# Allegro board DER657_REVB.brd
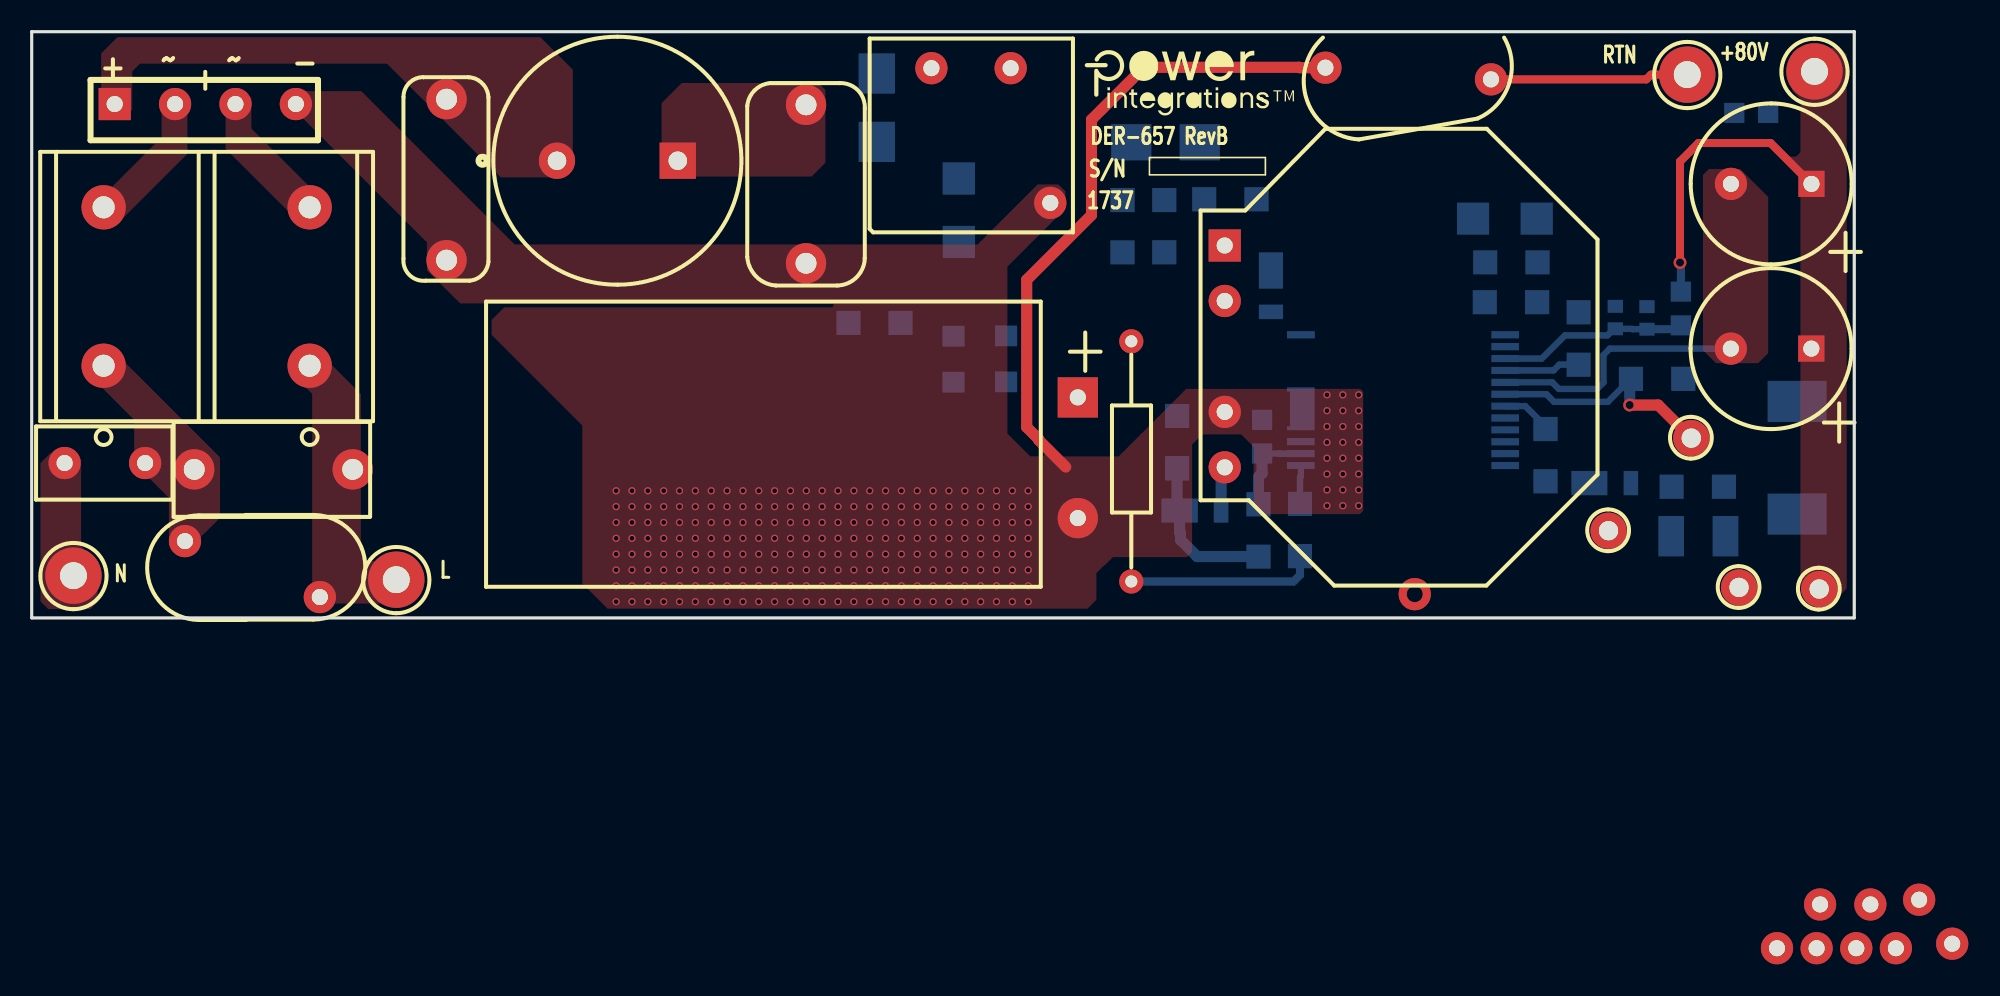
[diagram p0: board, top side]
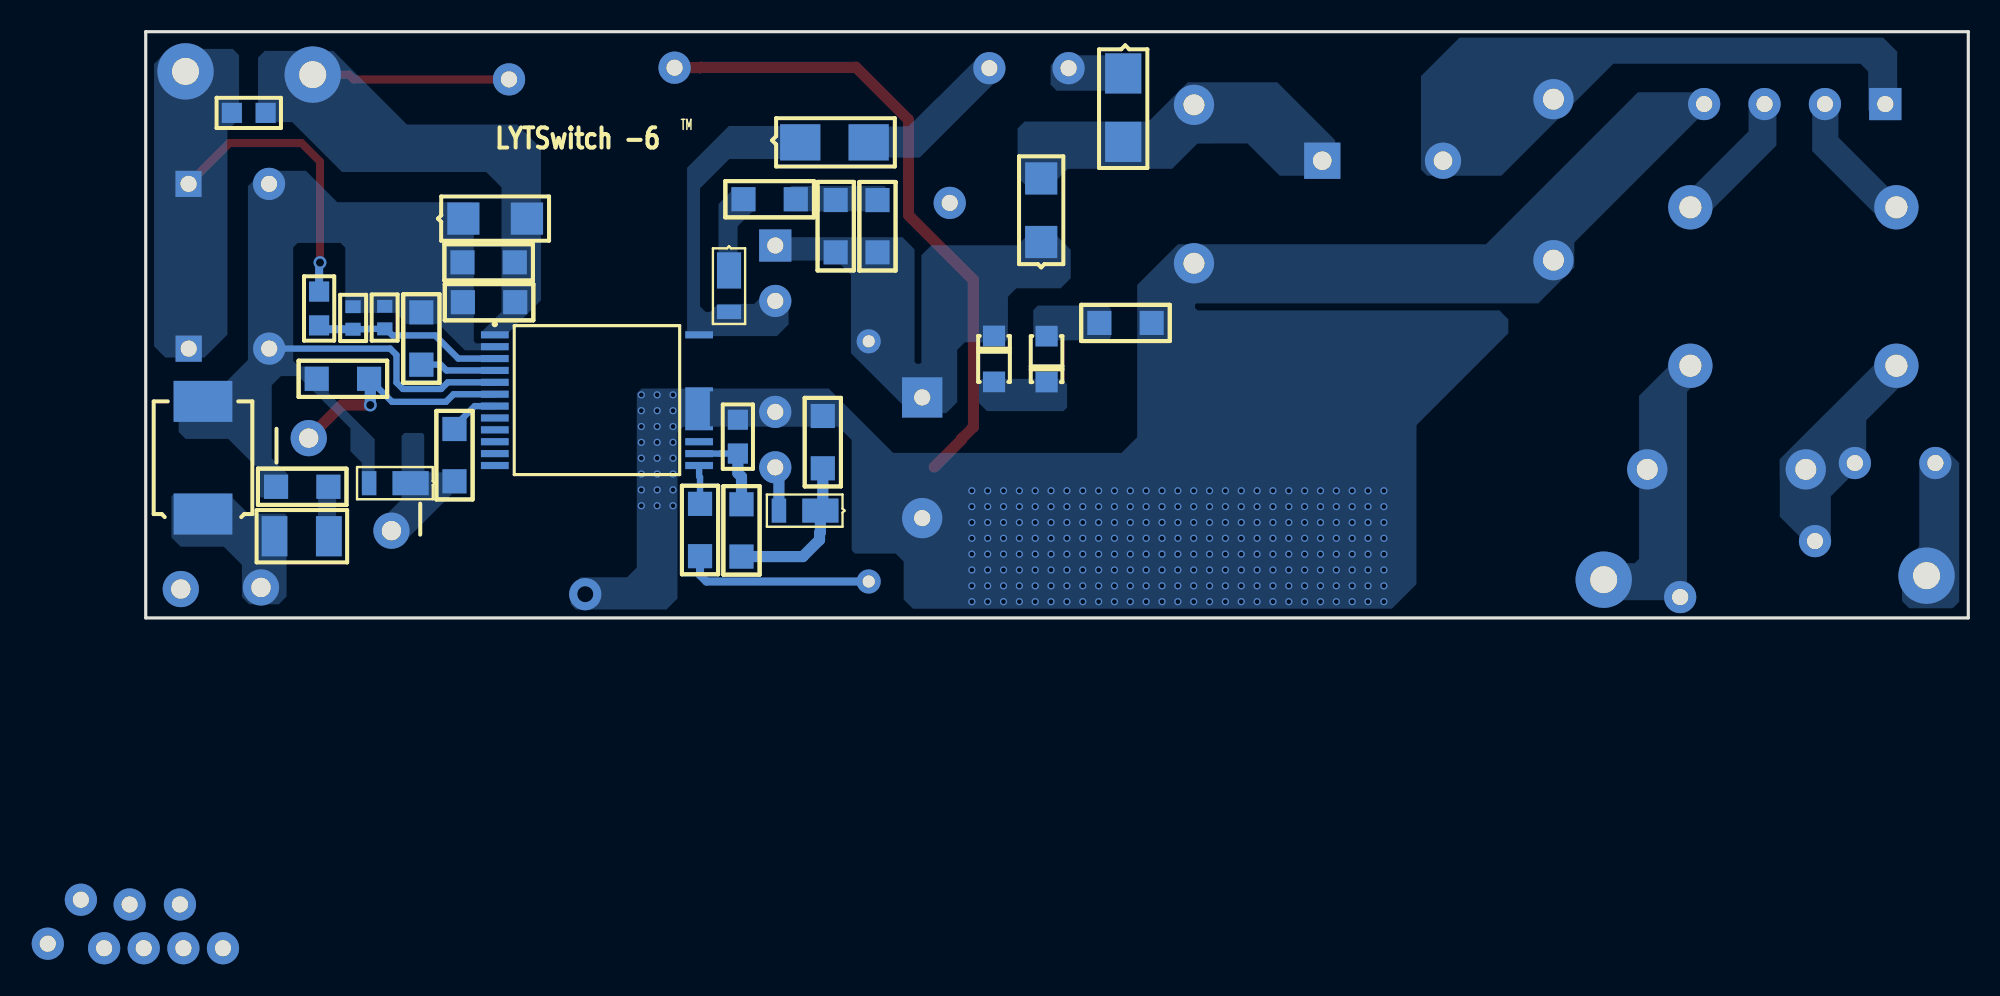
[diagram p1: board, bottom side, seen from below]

Outline 115 x 37 mm; copper layers: TOP, BOTTOM. Coordinates in mm from the lower left corner of the outline.
Outline path: 0,37 0,0 115,0 115,37 0,37

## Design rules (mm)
constraint set DEFAULT: min track width 0.508

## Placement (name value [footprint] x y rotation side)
BR1  UD4KB100-BP  [PIDAXBRIDGED3K]  5.24 32.43 0 top
C1  100 nF  [PI_NP_CAP492X236LS394D040]  20.26 9.38 180 top
C2  220 nF  [PI_NP_CAP_RAD470X220LS400D40]  26.18 32.74 270 top
C3  330 nF  [PI_NP_CAPRAD512X299LS394D040]  48.86 32.38 270 top
C4  120 uF  [PIPOLCAPCLYD710LS300040]  66.01 13.92 270 top
C9  1000 pF  [PISMC1206]  68.83 26.37 270 bottom
C10  22 uF  [PISMC1206]  72.28 9.44 90 bottom
C11  4.7 uF  [PISMC0805]  77.64 10.37 90 bottom
C12  3.3 nF  [PINPYCAPRAD540X290LS400040]  81.63 34.73 10 top
C13  2.2 uF  [PISMC1206]  97.61 19.29 270 bottom
C14  100 pF  [PISMC1206]  103.47 8.28 0 bottom
C15  10 uF  [PISMC1206]  100.91 15.09 0 bottom
C16  100 uF  [PIPOLCAPCYLD400LS200040]  112.29 17 180 top
C18  100 uF  [PIPOLCAPCYLD400LS200040]  112.3 27.39 180 top
C19  330 pF  [PISMC0603]  99.92 19.67 270 bottom
C37  1.5 nF  [PISMC0805]  109.57 31.87 180 bottom
D1  ES2J-LTP  [PISMDO214AC12]  53.32 34.36 270 bottom
D7  DFLR1200-7  [PISMDDFLR120012]  72.41 6.77 180 bottom
D8  DFLR1600-7  [PISMDDFLR120012]  78.2 21.96 90 bottom
D10  STTH3R06S  [PISMDO214AB12]  111.39 6.55 90 bottom
D11  DFLU1400-7  [PISMDDFLR120012]  98.26 8.51 180 bottom
D13  US1B  [PISMDSMA]  94.96 25.2 180 bottom
D16  S1J-13-F  [PISMDSMA]  58.5 23.73 90 bottom
D17  ES2J-LTP  [PISMDO214AC12]  73.7 30.02 180 bottom
F1  3.15 A  [PI_RST_MICROFUSE]  2.08 9.78 0 top
FL1  Hole_50mils  [PI_HOLE_50MIL]  112.79 1.82 0 top
FL2  Hole_50mils  [PI_HOLE_50MIL]  107.73 1.92 0 top
FL3  Hole_50mils  [PI_HOLE_50MIL]  99.49 5.51 0 top
FL4  Hole_50mils  [PI_HOLE_50MIL]  104.72 11.35 0 top
L2  20 mH  [PIIND4PKEMETSS21V]  17.54 15.92 180 top
L3  560 uh  [PI_CHOKE_RL5480-5_D2]  40.77 28.86 180 top
NOREF  -  []  66.46 36.27 0 top
NOREF#2  -  []  115 0 90 top
NOREF#3  -  []  0 0 0 top
NOREF#4  -  []  -140.78 54.23 0 top
NOREF#5  -  []  -218.6 -144.78 0 top
R4  2.0 M  [PI14WVRESD100LS100D030]  69.38 14.96 270 top
R17  510 k  [PISMR1206]  71.46 23.07 90 bottom
R18  10 k  [PISMR1206]  77.41 3.87 90 bottom
R22  47  [PISMR1206]  95.52 8.62 90 bottom
R24  6.2  [PISMR1206]  91.71 22.44 0 bottom
R29  102 k  [PISMR0805]  104.06 20.6 270 bottom
R30  1.62 k  [PISMR0603]  101.92 18.22 90 bottom
R43  0.062  [PISMR1206]  91.69 19.93 0 bottom
R45  2.00 M  [PISMR1206]  80.02 3.9 90 bottom
R46  20  [PISMR1206]  73.98 26.43 0 bottom
R47  4.7 k  [PISMR1206]  54.83 18.62 180 bottom
R48  100  [PISMR1210]  106.88 5.16 180 bottom
RV1  275 Vac  [PIDISC500X225LS335X140040]  9.67 4.85 0 top
T1  EE13  [PI_BOBBIN_EE13V_10P]  54.27 26.19 0 top
T2  RM10  [PI_BOBBIN_RM10_5P]  75.28 23.5 0 top
TP1  BLK  [PITPKEYSTONE125X125]  23 2.41 0 top
TP2  WHT  [PITPKEYSTONE125X125]  2.63 2.67 0 top
TP3  BLK  [PITPKEYSTONE125X125]  112.49 34.49 0 top
TP4  BLK  [PITPKEYSTONE125X125]  104.46 34.29 0 top
U4  LYT-6  [PI_IC_INSOP_24D]  92.97 17.87 180 bottom
VR1  BZD27C200P  [PISMDO219AB12]  61.48 17.8 270 bottom
VR2  BZD27C200P  [PISMDO219AB12]  58.16 14.88 90 bottom

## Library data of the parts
BR1 = DISCRETE BRIDGE_+~~-: alternate symbols: (pidaxbridgeD3K_horz)
C1 C2 C9-C11 C13-C15 C19 C37 = CAP NP
C3 = CAP NP: alternate symbols: (pi_np_caprad512x299ls394d040_h)
C4 = CAP POL: alternate symbols: (pipolcapd710ls3000401600lhoriz); tolerance: 20
C12 = CAP NP: alternate symbols: (pinpycaprad540x290ls400040h)
C16 C18 = CAP POL: alternate symbols: (pipolcapcyld400ls200040800h)
D1 D7 D8 D10 D11 D13 D16 D17 = DIODE
F1 = FUSE: alternate symbols: (pirstmicrofusehoz)
FL1-FL4 = FlyingLead
L2 = INDUCTOR_4P_revF
L3 = INDUCTOR_dot2: alternate symbols: (pi_choke_RL5480-5H_d2)
R4 = R: alternate symbols: (pi14wvresd100ls200d030,pi14wresd100ls400d030,pi14wresd100ls500d030)
R17 R18 R22 R29 R30 R43 R45-R48 = R
R24 = R: alternate symbols: (pismr1206_1)
RV1 = VARISTOR
T1 = BEE13/10PINS/GENERIC
T2 = BRM10_5P/GENERIC: alternate symbols: (pi_bobbin_rm10_5p_clp)
TP1-TP4 = TESTPOINT
U4 = DEV_Inno3CE
VR1 VR2 = DIODE_ZENER

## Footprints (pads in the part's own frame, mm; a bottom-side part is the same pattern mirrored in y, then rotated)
PI14WVRESD100LS100D030
  round 1.524 hole 0.762: 1(-2.5,0) 2(12.66,0)
PI_BOBBIN_EE13V_10P
  round 2.032 hole 1.016: 1(55.855,-47.041) 2(58.354,-47.041) 3(60.856,-47.041) 4(63.355,-47.041) 5(10,0) 6(66.909,-46.757) 7(7.501,8.501) 8(61.745,-44.28) 9(2.499,8.501) 10(58.572,-44.28)
PI_BOBBIN_RM10_5P
  rect 2.032x2.032 hole 1.016: 1(0,0)
  round 2.032 hole 1.016: 2(0,-3.5) 3(43.815,-41.29) 4(0,-10.5) 5(0,-14.001)
PI_CHOKE_RL5480-5_D2
  rect 2.286x2.286 hole 1.168: 1(0,0)
  round 2.286 hole 1.168: 2(7.62,0)
PI_HOLE_50MIL
  round 2.286 hole 1.219: 1(0,0)
PI_IC_INSOP_24D
  rect 1.75x0.45 smd: 1(0,0) 2(0,-0.75) 3(0,-1.5) 4(0,-2.25) 5(0,-3) 6(0,-3.75) 7(0,-4.5) 8(0,-5.25) 9(0,-6) 10(0,-6.75) 11(0,-7.5) 12(0,-8.25) 13(12.89,-8.25) 14(12.89,-7.5) 15(12.89,-6.75) 24(12.89,0)
  custom 0.438x0.438 smd: 16(12.89,-4.67)
PI_NP_CAP492X236LS394D040
  round 2.54 hole 1.321: 1(0,0) 2(10,0)
PI_NP_CAP_RAD470X220LS400D40
  round 2.54 hole 1.321: 1(0,0) 2(10.16,0)
PI_NP_CAPRAD512X299LS394D040
  round 2.54 hole 1.321: 1(0,0) 2(10,0)
PI_RST_MICROFUSE
  round 2.032 hole 1.016: 1(0,0) 2(5.08,0)
PIDAXBRIDGED3K
  rect 2.032x2.032 hole 1.016: 1(0,0)
  round 2.032 hole 1.016: 2(3.81,0) 3(7.62,0) 4(11.43,0)
PIDISC500X225LS335X140040
  round 2.032 hole 1.016: 1(0,0) 2(8.509,-3.531)
PIIND4PKEMETSS21V
  round 2.794 hole 1.397: 1(0,0) 2(13,0) 3(0,-10) 4(13,-10)
PINPYCAPRAD540X290LS400040
  round 2.032 hole 1.016: 1(0,0) 2(10.16,-2.54)
PIPOLCAPCLYD710LS300040
  rect 2.54x2.54 hole 1.016: 1(0,0)
  round 2.54 hole 1.016: 2(7.62,0)
PIPOLCAPCYLD400LS200040
  rect 1.651x1.651 hole 1.016: 1(0,0)
  round 2.032 hole 1.016: 2(5.08,0)
PISMC0603
  rect 0.813x0.965 smd: 1(0,0) 2(1.422,0)
PISMC0805
  rect 1.27x1.27 smd: 1(0,0) 2(2.134,0)
PISMC1206
  rect 1.524x1.524 smd: 1(0,0) 2(3.302,0)
PISMDDFLR120012
  rect 2.286x1.524 smd: 1(-0.025,0)
  rect 0.914x1.524 smd: 2(-2.642,0)
PISMDO214AB12
  rect 2.591x3.708 smd: 1(0,0) 2(7.112,0)
PISMDO214AC12
  rect 2.54x2.286 smd: 1(0,0) 2(4.318,0)
PISMDO219AB12
  rect 1.3x1.4 smd: 1(0,0) 2(2.9,0)
PISMDSMA
  rect 2.032x2.032 smd: 1(0,0) 2(4.013,0)
PISMR0603
  rect 0.813x0.965 smd: 1(0,0) 2(1.422,0)
PISMR0805
  rect 1.27x1.27 smd: 1(0,0) 2(2.134,0)
PISMR1206
  rect 1.524x1.524 smd: 1(0,0) 2(3.302,0)
PISMR1210
  rect 1.626x2.54 smd: 1(0,0) 2(3.429,0)
PITPKEYSTONE125X125
  round 3.556 hole 1.702: 1(0,0)

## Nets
GND: C13.1 C14.2 C15.2 C16.2 C18.2 C19.1 D10.2 D11.2 D13.1 R24.2 R30.2 R43.2 U4.2 U4.5
NC8: U4.8
NC9: U4.9
NC10: U4.10
NC11: U4.11
NC12: U4.12
NC15: U4.15
N10967118: C10.1 D7.1 R18.1
N10967192: D8.1 R46.2
N10967208: D11.1 FL3.1 R22.1
N10967232: C15.1 FL4.1 U4.6
N10967272: D8.2 D17.1 T2.2 U4.24
N10967292: C4.1 C9.2 D16.1 R4.1 R17.1 T2.1 VR1.1
N10967352: C11.1 R18.2 U4.14
N10967360: C19.2 R29.2 R30.1 U4.3
N10967588: C16.1 C18.1 C37.1 FL1.1 R29.1 TP3.1
N10967612: C12.2 C37.2 D13.2 R24.1 R43.1 TP4.1 U4.1
N10967616: D10.1 FL2.1 R48.1
N10968210: C14.1 R48.2
N10968562: BR1.4 C2.2 C3.2 C4.2 C10.2 C11.2 C12.1 R47.2 T1.5 T2.4 U4.16
N10970465: BR1.2 L2.4
N10970513: C1.2 F1.2 L2.2 RV1.1
N10971495: BR1.3(AC2) L2.3
N10975943: C9.1 R17.2 R46.1
N11160740: D7.2 T2.5
N11207739: C1.1 L2.1 RV1.2 TP1.1
N11231482: R22.2 U4.7
N11317958: R45.2 U4.13(VPIN)
N11319179: C13.2 U4.4
N11446006: D1.1 T1.9
N11450999: C3.1 D1.2 D16.2 L3.1
N11451346: R4.2 R45.1
N11459929: BR1.1 C2.1 L3.2
N11463653: D17.2 T1.7
N11465077: F1.1 TP2.1
N11473887: VR1.2 VR2.1
N11473996: R47.1 VR2.2

Pads without a net: T1 1 2 3 4 6 8 10; T2 3

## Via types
v1: diameter 0.813, hole 0.508, TOP to BOTTOM, 2 vias
v2: diameter 0.457, hole 0.305, TOP to BOTTOM, 240 vias
v3: diameter 2.032, hole 1.016, TOP to BOTTOM, 1 via

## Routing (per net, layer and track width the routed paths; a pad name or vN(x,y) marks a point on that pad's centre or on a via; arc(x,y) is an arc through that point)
GND: length 16.5
  BOTTOM w0.4: C16.2 99.58,17 99.18,16.6 99.18,14.86 98.77,14.45 96.36,14.45 95.94,14.87 U4.5
N10967118: length 10
  BOTTOM w0.7: C10.1 72.28,6.93 D7.1 72.43,5.41 72.48,5.35 72.48,4.93 73.54,3.87 R18.1
N10967232: length 15.1
  TOP w0.7: FL4.1 102.63,13.44 v1(100.83,13.44)
  BOTTOM w0.4: U4.6 95.57,14.12 96.06,13.64 99.46,13.64 100.83,15.01
  BOTTOM w0.7: v1(100.83,13.44) 100.83,15.01 C15.1
N10967352: length 5.7
  BOTTOM w0.4: U4.14 78.73,10.37 78.73,10.37 C11.1
  BOTTOM w0.7: C11.1 77.64,9.14 77.41,8.91 R18.2
N10967360: length 12
  BOTTOM w0.4: R30.1 100.98,18.22 100.96,18.24 C19.2 99.84,18.24 99.43,17.83 96.74,17.83 95.28,16.37 U4.3
  BOTTOM w0.508: R29.2 103.82,18.22 R30.1
N10967588: length 18.1
  TOP w0.508: C18.1 109.72,29.97 105.17,29.97 104.01,28.8 v1(104.01,22.43)
  BOTTOM w0.508: v1(104.01,22.43) 104.06,22.37 R29.1
N10967612: length 12.5
  TOP w0.508: TP4.1 102.18,34.29 101.88,33.99 C12.2
N10968562: length 40.8
  TOP w0.7: C12.1 80.01,34.73 79.99,34.75 70.18,34.75 66.87,31.45 66.87,25.43 62.78,21.34 62.78,12.04 63.54,11.28 63.54,11.23 65.25,9.53
  vias: v2(36.88,8.03) v2(36.88,7.03) v2(36.88,6.03) v2(36.88,5.03) v2(36.88,4.03) v2(36.88,3.03) v2(36.88,2.03) v2(36.88,1.03) v2(37.88,8.03) v2(37.88,7.03) v2(37.88,6.03) v2(37.88,5.03) v2(37.88,4.03) v2(37.88,3.03) v2(37.88,2.03) v2(37.88,1.03) v2(38.88,8.03) v2(38.88,7.03) v2(38.88,6.03) v2(38.88,5.03) v2(38.88,4.03) v2(38.88,3.03) v2(38.88,2.03) v2(38.88,1.03) v2(39.88,8.03) v2(39.88,7.03) v2(39.88,6.03) v2(39.88,5.03) v2(39.88,4.03) v2(39.88,3.03) v2(39.88,2.03) v2(39.88,1.03) v2(40.88,8.03) v2(40.88,7.03) v2(40.88,6.03) v2(40.88,5.03) v2(40.88,4.03) v2(40.88,3.03) v2(40.88,2.03) v2(40.88,1.03) v2(41.88,8.03) v2(41.88,7.03) v2(41.88,6.03) v2(41.88,5.03) v2(41.88,4.03) v2(41.88,3.03) v2(41.88,2.03) v2(41.88,1.03) v2(42.88,8.03) v2(42.88,7.03) v2(42.88,6.03) v2(42.88,5.03) v2(42.88,4.03) v2(42.88,3.03) v2(42.88,2.03) v2(42.88,1.03) v2(43.88,8.03) v2(43.88,7.03) v2(43.88,6.03) v2(43.88,5.03) v2(43.88,4.03) v2(43.88,3.03) v2(43.88,2.03) v2(43.88,1.03) v2(44.88,8.03) v2(44.88,7.03) v2(44.88,6.03) v2(44.88,5.03) v2(44.88,4.03) v2(44.88,3.03) v2(44.88,2.03) v2(44.88,1.03) v2(45.88,8.03) v2(45.88,7.03) v2(45.88,6.03) v2(45.88,5.03) v2(45.88,4.03) v2(45.88,3.03) v2(45.88,2.03) v2(45.88,1.03) v2(46.88,8.03) v2(46.88,7.03) v2(46.88,6.03) v2(46.88,5.03) v2(46.88,4.03) v2(46.88,3.03) v2(46.88,2.03) v2(46.88,1.03) v2(47.88,8.03) v2(47.88,7.03) v2(47.88,6.03) v2(47.88,5.03) v2(47.88,4.03) v2(47.88,3.03) v2(47.88,2.03) v2(47.88,1.03) v2(48.88,8.03) v2(48.88,7.03) v2(48.88,6.03) v2(48.88,5.03) v2(48.88,4.03) v2(48.88,3.03) v2(48.88,2.03) v2(48.88,1.03) v2(49.88,8.03) v2(49.88,7.03) v2(49.88,6.03) v2(49.88,5.03) v2(49.88,4.03) v2(49.88,3.03) v2(49.88,2.03) v2(49.88,1.03) v2(50.88,8.03) v2(50.88,7.03) v2(50.88,6.03) v2(50.88,5.03) v2(50.88,4.03) v2(50.88,3.03) v2(50.88,2.03) v2(50.88,1.03) v2(51.88,8.03) v2(51.88,7.03) v2(51.88,6.03) v2(51.88,5.03) v2(51.88,4.03) v2(51.88,3.03) v2(51.88,2.03) v2(51.88,1.03) v2(52.88,8.03) v2(52.88,7.03) v2(52.88,6.03) v2(52.88,5.03) v2(52.88,4.03) v2(52.88,3.03) v2(52.88,2.03) v2(52.88,1.03) v2(53.88,8.03) v2(53.88,7.03) v2(53.88,6.03) v2(53.88,5.03) v2(53.88,4.03) v2(53.88,3.03) v2(53.88,2.03) v2(53.88,1.03) v2(54.88,8.03) v2(54.88,7.03) v2(54.88,6.03) v2(54.88,5.03) v2(54.88,4.03) v2(54.88,3.03) v2(54.88,2.03) v2(54.88,1.03) v2(55.88,8.03) v2(55.88,7.03) v2(55.88,6.03) v2(55.88,5.03) v2(55.88,4.03) v2(55.88,3.03) v2(55.88,2.03) v2(55.88,1.03) v2(56.88,8.03) v2(56.88,7.03) v2(56.88,6.03) v2(56.88,5.03) v2(56.88,4.03) v2(56.88,3.03) v2(56.88,2.03) v2(56.88,1.03) v2(57.88,8.03) v2(57.88,7.03) v2(57.88,6.03) v2(57.88,5.03) v2(57.88,4.03) v2(57.88,3.03) v2(57.88,2.03) v2(57.88,1.03) v2(58.88,8.03) v2(58.88,7.03) v2(58.88,6.03) v2(58.88,5.03) v2(58.88,4.03) v2(58.88,3.03) v2(58.88,2.03) v2(58.88,1.03) v2(59.88,8.03) v2(59.88,7.03) v2(59.88,6.03) v2(59.88,5.03) v2(59.88,4.03) v2(59.88,3.03) v2(59.88,2.03) v2(59.88,1.03) v2(60.88,8.03) v2(60.88,7.03) v2(60.88,6.03) v2(60.88,5.03) v2(60.88,4.03) v2(60.88,3.03) v2(60.88,2.03) v2(60.88,1.03) v2(61.88,8.03) v2(61.88,7.03) v2(61.88,6.03) v2(61.88,5.03) v2(61.88,4.03) v2(61.88,3.03) v2(61.88,2.03) v2(61.88,1.03) v2(62.88,8.03) v2(62.88,7.03) v2(62.88,6.03) v2(62.88,5.03) v2(62.88,4.03) v2(62.88,3.03) v2(62.88,2.03) v2(62.88,1.03) v2(81.73,14.08) v2(81.73,13.08) v2(81.73,12.08) v2(81.73,11.08) v2(81.73,10.08) v2(81.73,9.08) v2(81.73,8.08) v2(81.73,7.08) v2(82.73,14.08) v2(82.73,13.08) v2(82.73,12.08) v2(82.73,11.08) v2(82.73,10.08) v2(82.73,9.08) v2(82.73,8.08) v2(82.73,7.08) v2(83.73,14.08) v2(83.73,13.08) v2(83.73,12.08) v2(83.73,11.08) v2(83.73,10.08) v2(83.73,9.08) v2(83.73,8.08) v2(83.73,7.08) v3(87.27,1.5)
N11160740: length 2.8
  BOTTOM w0.7: T2.5 75.05,9.27 D7.2
N11231482: length 3.2
  BOTTOM w0.4: R22.2 95.52,12.09 94.24,13.37 U4.7
N11317958: length 2.4
  BOTTOM w0.4: R45.2 80.02,8.88 80.08,8.94 U4.13
N11319179: length 4.8
  BOTTOM w0.4: U4.4 96.03,15.62 96.39,15.98 C13.2
N11451346: length 12
  BOTTOM w0.508: R4.2 79.62,2.3 80.02,2.7 R45.1

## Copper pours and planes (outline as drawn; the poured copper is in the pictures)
GND on TOP: 106.27,16.08 108.93,16.08 109.57,16.71 109.57,26.57 107.8,28.33 105.83,28.33 105.45,27.95 105.45,16.89
GND on BOTTOM: 106.16,7.59 106.04,7.72 106.04,9.07 107.05,10.08 107.05,14.68 106.47,15.27 105.38,15.27 102.09,11.98 102.09,10.53 101.36,9.8 101.36,7.9 101.24,7.77 100.7,7.77 100.55,7.92 100.55,11.28 103.45,14.17 103.45,15.82 103.5,15.88 105.34,15.88 105.69,16.23 105.69,23.38 105.4,23.67 102.71,23.67 102.41,23.37 102.41,19.38 102.28,19.25 99.23,19.25 98.52,18.54 96.51,18.54 94.86,16.89 92.37,16.89 92.27,16.99 92.27,17.17 92.42,17.32 94.15,17.32 94.3,17.48 94.3,26.06 94.48,26.24 102.91,26.24 104.89,28.22 107.59,28.22 108.55,27.25 108.55,16.28 109.97,14.86 112.69,14.86 112.92,14.63 112.92,11.73 112.49,11.3 109.8,11.3 107.94,9.45 107.94,7.82 107.71,7.59
N10967192 on BOTTOM: 78.86,26.12 78.86,21.12 78.71,20.96 77.82,20.96 77.65,21.13 77.65,24.71 76.56,25.8 76.56,27.11 77.87,27.11
N10967208 on BOTTOM: 95.06,9.19 97.27,9.19 97.43,9.35 97.43,11.56 97.54,11.67 98.67,11.67 98.86,11.49 98.86,7.49 100.32,6.02 100.32,4.8 100.04,4.52 98.98,4.52 95.04,8.46 95.04,9.17
N10967272 on BOTTOM: 80.74,17.79 80.84,17.89 80.84,28.41 78.2,31.05 72.56,31.05 72.56,29.07 72.66,28.97 78.17,28.97 80.03,27.11 80.03,19.67 79.67,19.31 79.39,19.31 78.88,19.82 76.6,19.82 75.72,20.7 74.82,20.7 74.44,20.32 74.44,18.53 75.18,17.79
N10967292 on BOTTOM: 70.5,16.71 66.72,12.93 64.48,12.93 63.8,13.61 63.8,16.92 63.31,17.4 60.8,17.4 60.6,17.6 60.6,20.27 60.06,20.8 57.27,20.8 56.63,21.44 56.63,23.24 57.7,24.31 59.2,24.31 59.99,23.52 65.42,23.52 66.06,22.89 66.06,16.13 66.15,16.04 66.36,16.04 66.49,16.17 66.49,23.27 67.25,24.03 75.66,24.03 76.12,23.57 76.12,22.73 75.94,22.56 71.39,22.56 70.5,21.67
N10967588 on TOP: 113.73,1.07 112.11,1.07 111.6,1.57 111.6,27.71 110.66,28.65 110.66,29.01 110.76,29.11 111.32,29.11 111.6,29.39 111.6,32.77 111.09,33.27 111.09,35.66 111.42,35.99 114.09,35.99 114.52,35.56 114.52,1.85
N10967588 on BOTTOM: 113.76,16.43 111.3,16.43 109.85,17.88 109.85,30.76 109.11,31.5 109.11,35.51 109.52,35.92 113.53,35.92 114.47,34.98 114.47,17.14
N10967612 on BOTTOM: 92.37,17.74 93.72,17.74 93.85,17.87 93.85,18.02 92.55,19.31 92.55,27.18 93.52,28.14 102.61,28.14 105.76,31.29 107.66,31.29 107.92,31.55 107.92,35.36 107.49,35.79 103.17,35.79 98.52,31.14 91.56,31.14 90.06,29.64 90.06,20.05
N10967616 on BOTTOM: 108.53,6.58 109.82,7.87 113.17,7.87 113.38,7.67 113.38,5.08 112.79,4.5 110.08,4.5 108.93,3.35 108.93,1.32 108.48,0.86 106.6,0.86 106.11,1.35 106.11,6.48 106.22,6.58
N10968210 on BOTTOM: 104.13,8.92 104.13,4.42 103.8,4.09 103.37,4.09 102.99,4.47 102.99,8.92 103.07,8.99 104.06,8.99
N10968562 on TOP: 68.57,10.19 65.02,10.19 64.76,10.44 63.98,10.44 63.98,10.38 63.8,10.2 63,10.2 61.56,11.63 61.56,22.17 65.22,25.83 65.22,26.92 64.79,27.36 63.47,27.36 59.68,23.57 30.47,23.57 20.8,33.25 16.32,33.25 15.92,32.84 15.92,32 16.43,31.5 17.14,31.5 24.94,23.7 24.94,21.95 27.03,19.85 50.51,19.85 50.59,19.77 50.59,19.68 50.51,19.61 29.81,19.61 29.02,18.82 29.02,17.86 34.74,12.14 34.74,2.18 36.34,0.58 66.62,0.58 67.18,1.14 67.18,2.82 67.71,3.35 67.73,3.35 68.22,3.84 72.89,3.84 73.22,4.17 73.22,10.95 73.86,11.58 76.32,11.58 77.11,10.79 77.11,7.01 77.56,6.55 83.81,6.55 84.02,6.76 84.02,14.27 83.84,14.45 72.84,14.45
N10968562 on BOTTOM: 67.84,10.41 53.43,10.41 52.44,11.4 52.44,21.01 49.87,23.58 30.43,23.58 20.85,33.17 16.25,33.17 15.94,32.87 15.94,31.83 16.3,31.47 17.09,31.47 24.86,23.7 24.86,22.12 27.13,19.85 48.72,19.85 48.79,19.79 48.79,19.56 48.63,19.41 29.58,19.41 29.02,18.85 29.02,17.96 34.82,12.17 34.82,2.13 36.37,0.58 66.59,0.58 67.18,1.17 67.18,3.56 67.68,4.06 70.25,4.06 70.45,4.27 70.45,11.23 71.29,12.06 81.09,12.06 81.45,11.71 81.45,1.22 82.14,0.53 87.85,0.53 88.18,0.86 88.18,1.96 87.57,2.57 84.63,2.57 84.02,3.17 84.02,14.17 83.71,14.48 71.9,14.48
N10970465 on TOP: 4.03,26.67 4.54,26.67 8.2,30.33 8.2,32.87 8.55,33.22 9.52,33.22 9.82,32.92 9.82,29.29 5.43,24.89 4.16,24.89 3.78,25.27 3.78,26.42
N10970465 on BOTTOM: 4.5,27.19 3.88,26.57 3.88,25.22 4.18,24.92 5.3,24.92 9.85,29.46 9.85,32.82 9.44,33.22 8.55,33.22 8.2,32.87 8.2,30.33 5.06,27.19
N10970513 on TOP: 6.47,12.5 6.47,9.78 8.65,7.59 8.65,5.05 9.19,4.52 10.08,4.52 11.88,6.32 11.88,10.13 5.22,16.79 3.65,16.79 3.5,16.64 3.5,15.47
N10970513 on BOTTOM: 6.44,12.47 3.6,15.32 3.6,16.64 3.7,16.74 5.17,16.74 11.91,10.01 11.91,8.81 11.89,8.8 11.89,6.39 9.95,4.45 9.19,4.45 8.68,4.95 8.68,7.67 6.44,9.91
N10971495 on TOP: 12.24,32.87 12.24,29.62 16.88,24.97 18.08,24.97 18.59,25.48 18.59,26.59 17.92,27.25 17.49,27.25 13.86,30.89 13.86,32.82 13.48,33.2 12.57,33.2
N10971495 on BOTTOM: 12.11,32.84 12.11,29.82 16.93,24.99 18.18,24.99 18.51,25.32 18.51,26.62 17.98,27.15 17.42,27.15 13.86,30.71 13.86,32.74 13.43,33.17 12.44,33.17
N10975943 on BOTTOM: 68.17,27.03 68.17,25.84 68.34,25.66 74.34,25.66 74.57,25.89 74.57,26.96 74.26,27.26 68.39,27.26
N11207739 on TOP: 16.6,16.71 16.6,15.24 17.7,14.15 17.7,1.65 17.71,1.64 17.71,1.13 17.92,0.91 23.74,0.91 24.53,1.7 24.53,2.72 23.67,3.58 21.15,3.58 20.77,3.96 20.77,14.12 17.98,16.92 16.81,16.92
N11207739 on BOTTOM: 23.77,1.12 18.18,1.12 17.75,1.55 17.75,14.27 16.58,15.44 16.58,16.66 16.83,16.92 17.87,16.92 20.77,14.02 20.77,3.73 21.05,3.45 23.64,3.45 24.43,2.67 24.43,1.78
N11446006 on BOTTOM: 57.27,35.51 57.9,34.87 57.9,33.66 57.52,33.27 52.75,33.27 52.37,33.66 52.37,35.38 52.49,35.51
N11450999 on TOP: 49.22,27.86 50.08,28.73 50.08,33.32 49.65,33.76 41.01,33.76 39.74,32.49 39.74,28.07 39.95,27.86
N11450999 on BOTTOM: 45.48,29.95 47.65,29.95 47.66,29.94 48.64,29.94 50.23,28.35 56.81,28.35 58.03,27.13 59.3,27.13 59.99,27.81 59.99,30.89 59.54,31.33 51.72,31.33 49.24,33.81 43.6,33.81 39.95,30.15 39.95,28.14 40.18,27.91 43.45,27.91
N11459929 on TOP: 4.39,31.78 6.04,31.78 6.34,32.08 6.34,34.49 6.83,34.98 22.42,34.98 29.58,27.81 33.39,27.81 34.16,28.57 34.16,29.36 34.14,29.38 34.14,34.61 32.1,36.65 5.4,36.65 4.39,35.64
N11459929 on BOTTOM: 4.49,31.8 6.06,31.8 6.32,32.05 6.32,34.49 6.8,34.98 22.4,34.98 29.46,27.91 34.16,27.91 34.54,28.3 34.54,34.19 32.1,36.63 5.38,36.63 4.49,35.74
N11463653 on BOTTOM: 61.61,35.61 62.25,35.61 65.02,32.84 65.04,32.84 66.87,31.01 70.22,31.01 70.53,30.71 70.53,29.06 66.16,29.06 60.95,34.26 60.95,34.95
N11465077 on TOP: 3.7,0.56 1.03,0.56 0.55,1.04 0.55,9.78 1.19,10.41 2.71,10.41 3.12,10.01 3.12,4.52 4.16,3.48 4.16,1.02
N11465077 on BOTTOM: 2.71,10.41 1.21,10.41 0.58,9.78 0.58,1.02 0.98,0.61 3.73,0.61 4.18,1.07 4.18,3.43 3.09,4.52 3.09,10.03
N11473887 on BOTTOM: 57.22,15.09 62.25,15.09 62.43,14.91 62.43,13.56 61.92,13.06 57.09,13.06 56.86,13.28 56.86,14.73
N11473996 on BOTTOM: 58.64,17.53 54.27,17.53 54.09,17.7 54.09,19.25 54.11,19.27 54.11,19.52 54.3,19.71 58.72,19.71 59,19.43 59,17.88

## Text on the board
Ref Des/Silkscreen Bottom: TM | LYTSwitch -6
Ref Des/Silkscreen Top: N | L | 1737 | S/N | DER-657 RevB | RTN | +80V
PAGE_OUTLINE: 13   MATERIAL FR4 COPPER 2oz THICKNESS 0.062"
User.5: FIGURE | FINISHED_SIZE | 12.0 | 20.0 | 30.0 | 40.0 | 46.0 | 48.0 | 52.0 | 55.0 | 67.0 | DRILL CHART: TOP to BOTTOM | ALL UNITS ARE IN MILS | PLATED | QTY | 240 | 2 | 32 | 1 | 4 | 6
